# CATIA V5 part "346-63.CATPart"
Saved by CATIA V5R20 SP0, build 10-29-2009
Part number: 346-63
Definition: NONE
Nomenclature: 346-63
Source: Unknown
Description: 346-63
Bounding box of the stored display mesh (mm): x 0 to 99, y -60 to 60, z -60 to 60
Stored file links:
  C:\Users\Utente\Desktop\IO LAVORO\3D X SITO CF\X SITO\3D files 346\346-63.CATPart
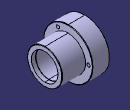
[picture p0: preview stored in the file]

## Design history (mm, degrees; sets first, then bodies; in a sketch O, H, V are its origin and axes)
Body1 "346-63" (main body)
  Solid1: solid without history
